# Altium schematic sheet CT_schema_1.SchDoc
size 714 x 518 mm
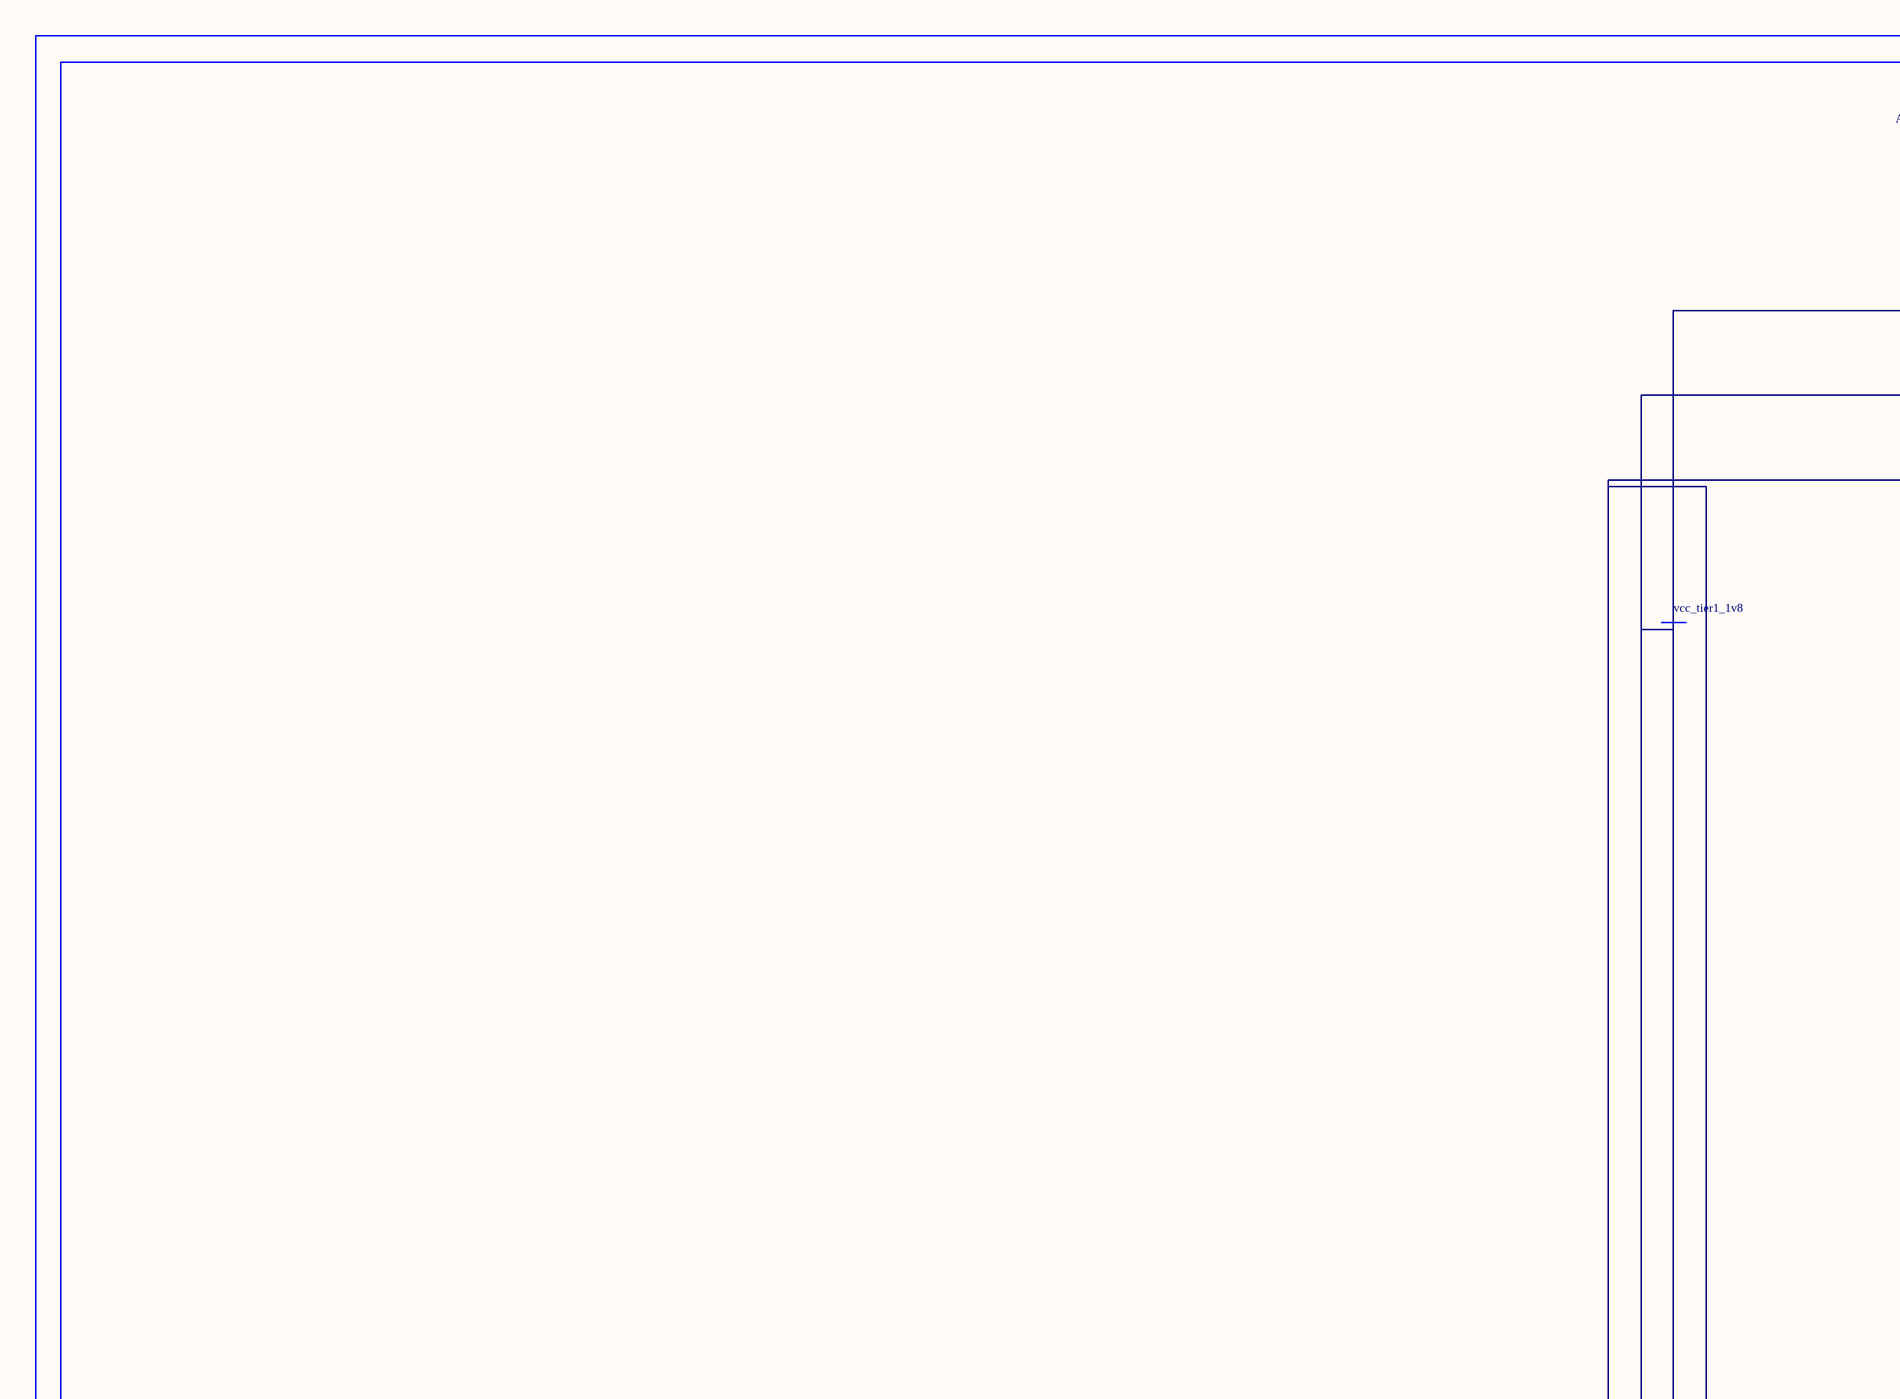
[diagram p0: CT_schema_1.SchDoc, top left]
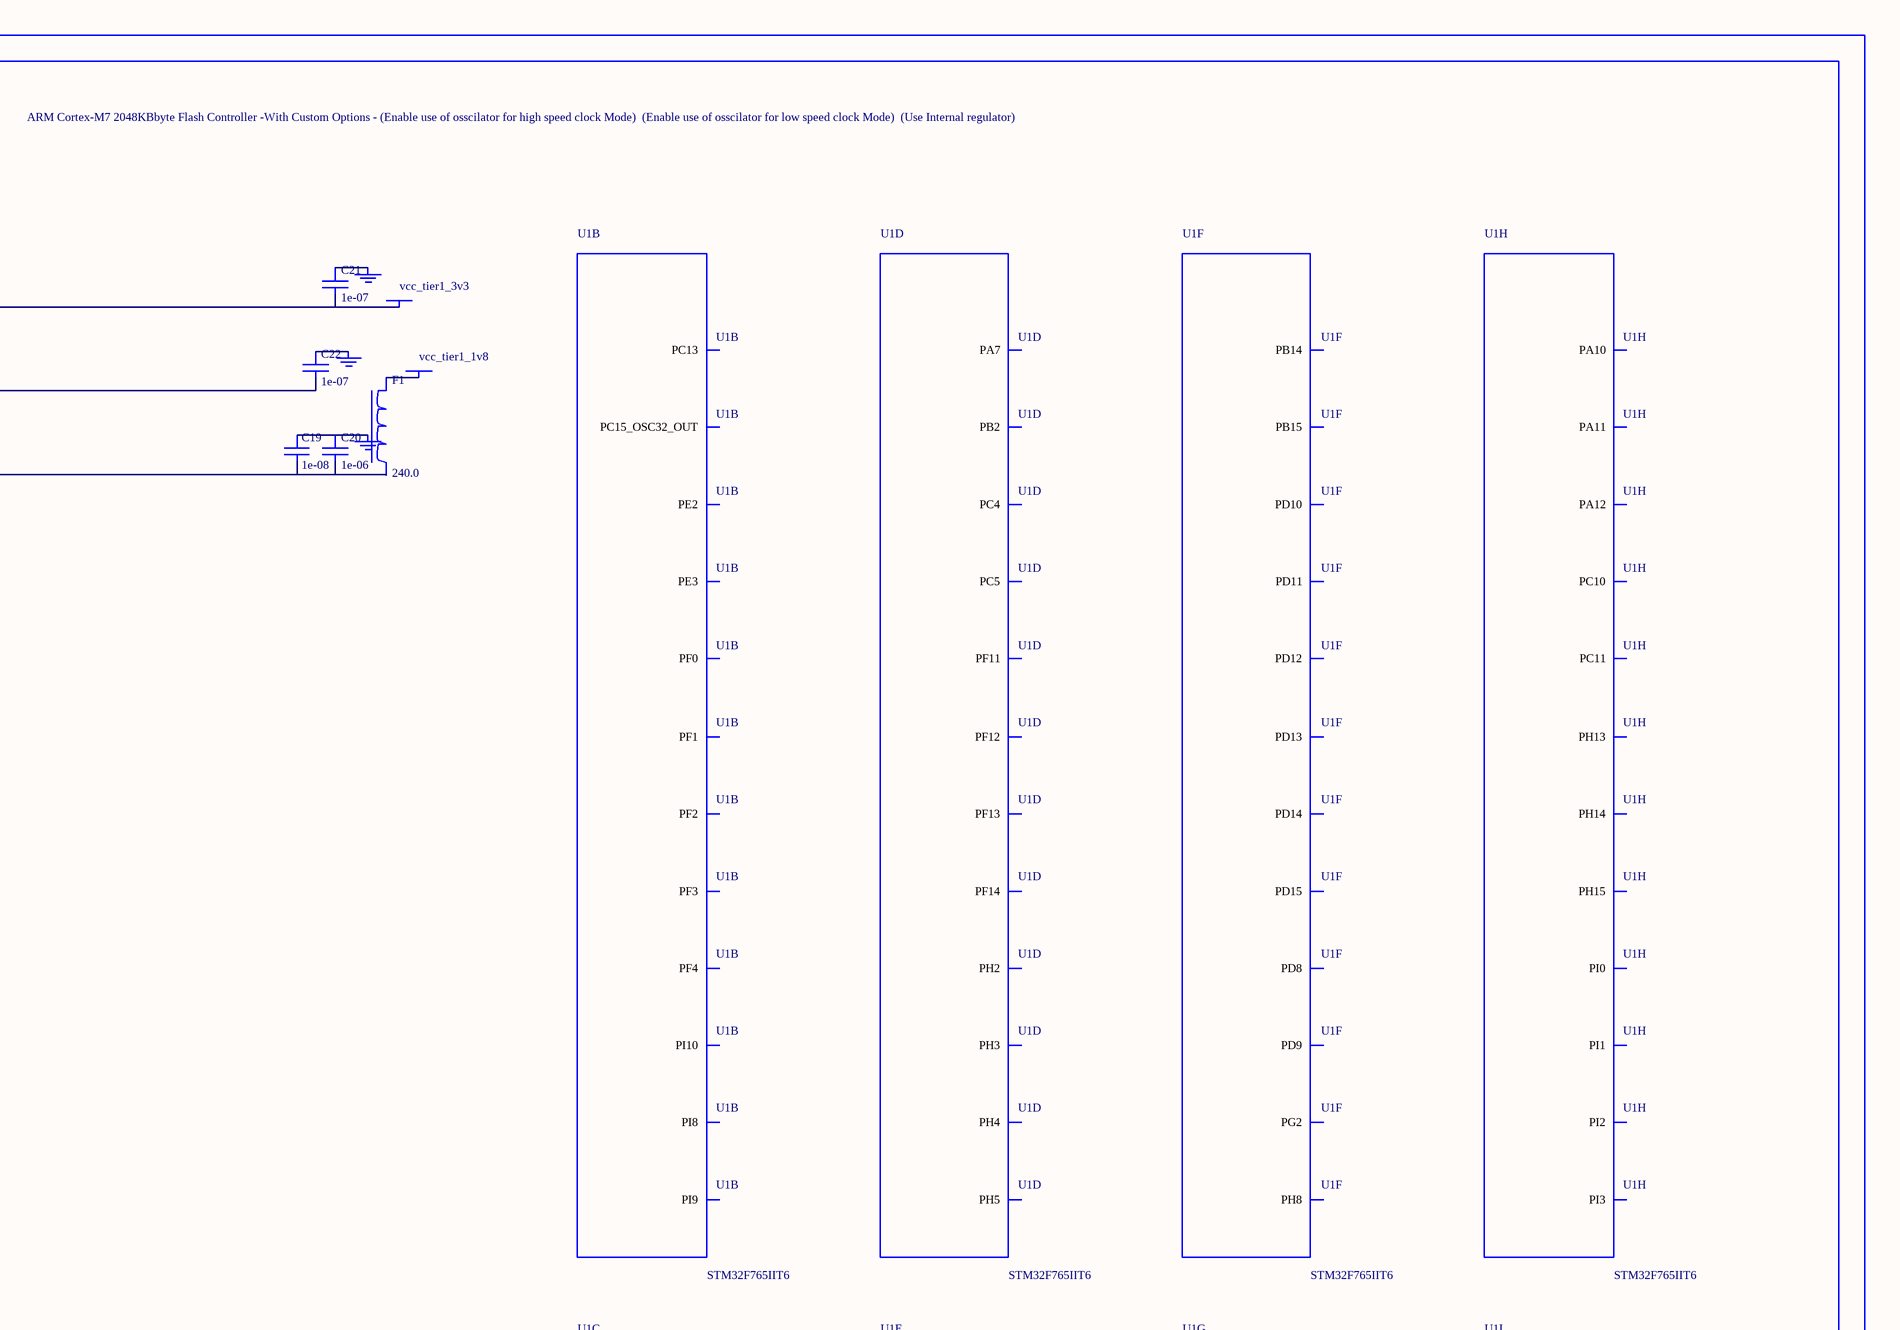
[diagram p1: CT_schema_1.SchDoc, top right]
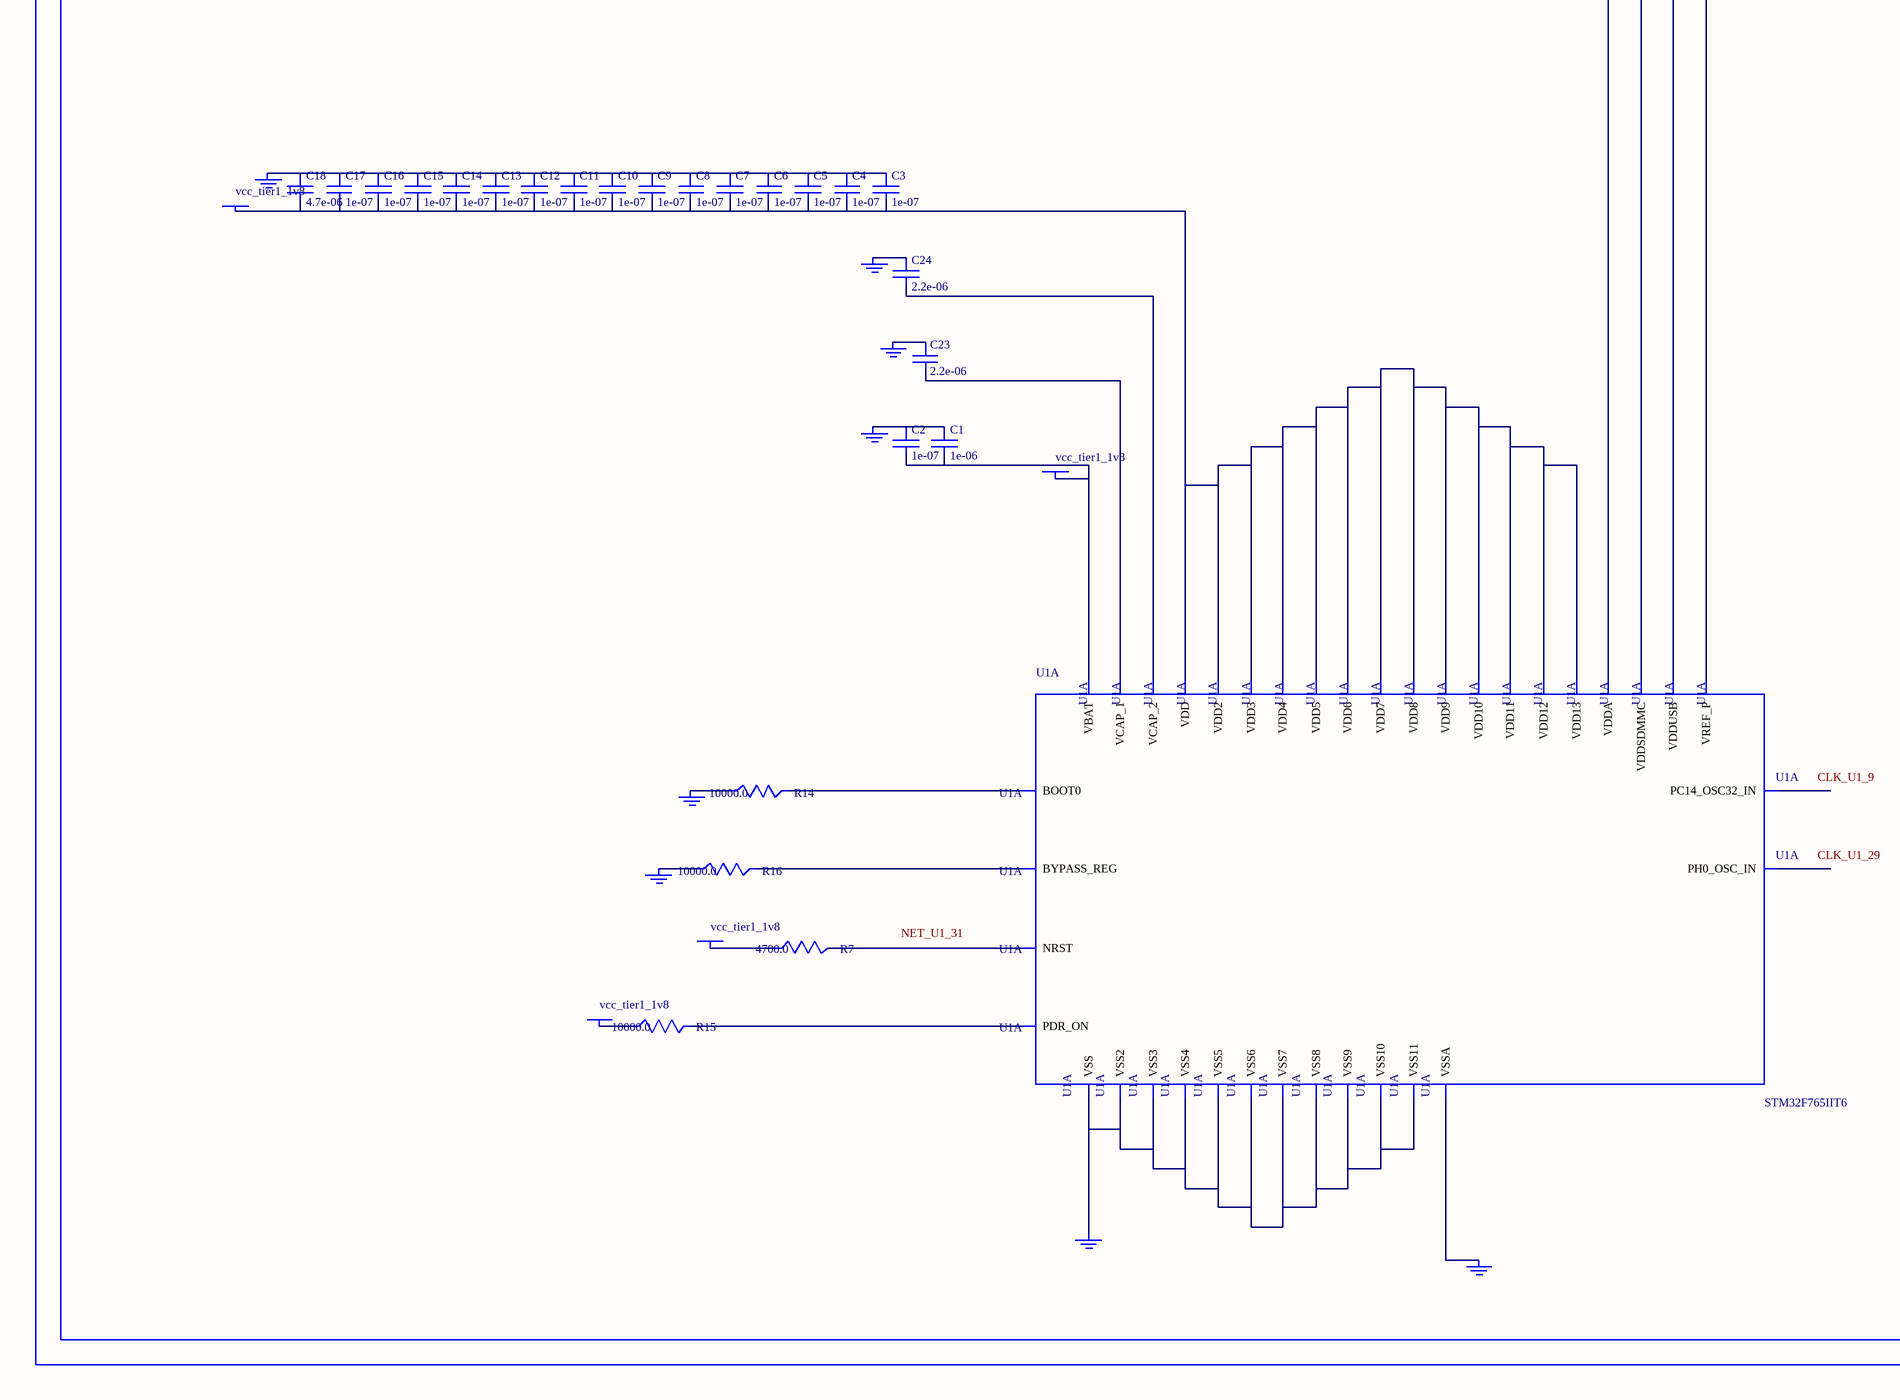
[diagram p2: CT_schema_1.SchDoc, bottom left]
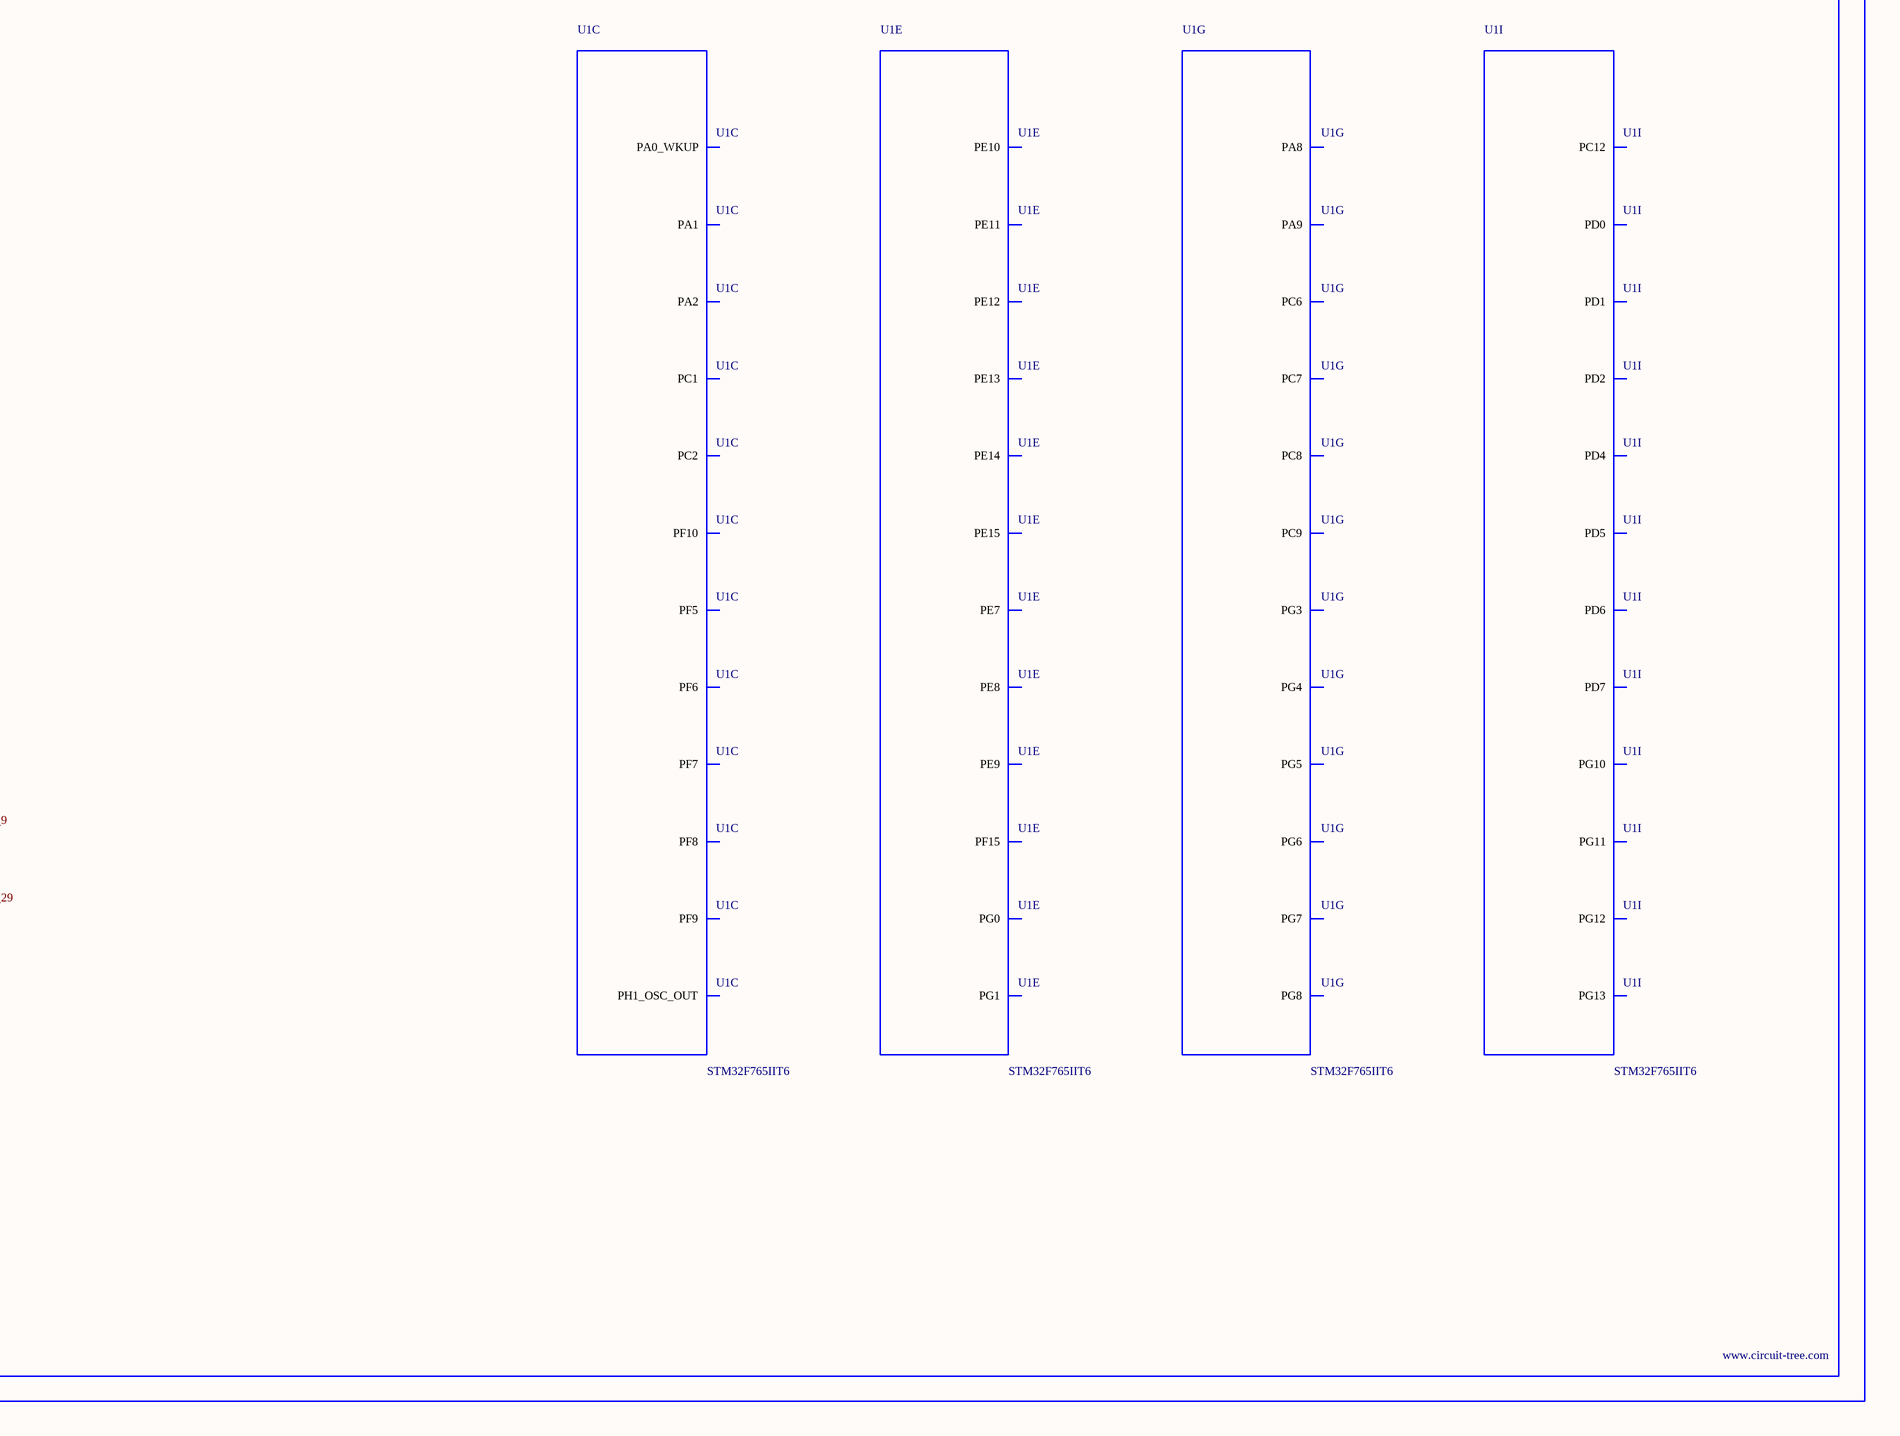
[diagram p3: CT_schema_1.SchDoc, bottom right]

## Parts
BORDER0  (no value)
C1  1e-06  [C0603]
C2  1e-07  [C0603]
C3  1e-07  [C0603]
C4  1e-07  [C0603]
C5  1e-07  [C0603]
C6  1e-07  [C0603]
C7  1e-07  [C0603]
C8  1e-07  [C0603]
C9  1e-07  [C0603]
C10  1e-07  [C0603]
C11  1e-07  [C0603]
C12  1e-07  [C0603]
C13  1e-07  [C0603]
C14  1e-07  [C0603]
C15  1e-07  [C0603]
C16  1e-07  [C0603]
C17  1e-07  [C0603]
C18  4.7e-06  [C0603]
C19  1e-08  [C0603]
C20  1e-06  [C0603]
C21  1e-07  [C0603]
C22  1e-07  [C0603]
C23  2.2e-06  [C0603]
C24  2.2e-06  [C0603]
F1  240.0  [L0603]
GND_INSTANCE_0_0  (no value)
GND_INSTANCE_0_1  (no value)
GND_INSTANCE_0_2  (no value)
GND_INSTANCE_0_3  (no value)
GND_INSTANCE_0_4  (no value)
GND_INSTANCE_0_5  (no value)
GND_INSTANCE_0_6  (no value)
GND_INSTANCE_0_7  (no value)
GND_INSTANCE_0_8  (no value)
GND_INSTANCE_0_9  (no value)
GND_INSTANCE_0_10  (no value)
POWER_INSTANCE_0_0  vcc_tier1_1v8
POWER_INSTANCE_0_1  vcc_tier1_1v8
POWER_INSTANCE_0_2  vcc_tier1_1v8
POWER_INSTANCE_0_3  vcc_tier1_3v3
POWER_INSTANCE_0_4  vcc_tier1_1v8
POWER_INSTANCE_0_5  vcc_tier1_1v8
POWER_INSTANCE_0_6  vcc_tier1_1v8
R7  4700.0  [R0603]
R14  10000.0  [R0603]
R15  10000.0  [R0603]
R16  10000.0  [R0603]
U1  STM32F765IIT6  [LQFP176]  (parts A,B,C,D,E,F,G,H,I of 12)

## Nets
NetC1_1: C1.1 C2.1 GND_INSTANCE_0_0.0(GND)
NetC1_2: C1.2 C2.2 POWER_INSTANCE_0_0.0(PWR) U1.6(VBAT)
NetC3_1: C3.1 C4.1 C5.1 C6.1 C7.1 C8.1 C9.1 C10.1 C11.1 C12.1 C13.1 C14.1 C15.1 C16.1 C17.1 C18.1 GND_INSTANCE_0_1.0(GND)
NetC3_2: C3.2 C4.2 C5.2 C6.2 C7.2 C8.2 C9.2 C10.2 C11.2 C12.2 C13.2 C14.2 C15.2 C16.2 C17.2 C18.2 POWER_INSTANCE_0_1.0(PWR) U1.15(VDD) U1.23(VDD2) U1.36(VDD3) U1.49(VDD4) U1.62(VDD5) U1.72(VDD6) U1.82(VDD7) U1.91(VDD8) U1.103(VDD9) U1.127(VDD10) U1.136(VDD11) U1.159(VDD12) U1.172(VDD13)
NetC19_1: C19.1 C20.1 GND_INSTANCE_0_3.0(GND)
NetC19_2: C19.2 C20.2 U1.38(VREF_P) U1.39(VDDA)
NetC21_1: C21.1 GND_INSTANCE_0_6.0(GND)
NetC21_2: C21.2 C22.2 POWER_INSTANCE_0_3.0(PWR) POWER_INSTANCE_0_4.0(PWR) U1.114(VDDUSB) U1.149(VDDSDMMC)
NetC22_1: C22.1 GND_INSTANCE_0_8.0(GND)
NetC23_1: C23.1 GND_INSTANCE_0_5.0(GND)
NetC23_2: C23.2 U1.81(VCAP_1)
NetC24_1: C24.1 GND_INSTANCE_0_7.0(GND)
NetC24_2: C24.2 U1.125(VCAP_2)
NetF1_1: F1.1 POWER_INSTANCE_0_2.0(PWR)
NetGND_INSTANCE_0_2_0: GND_INSTANCE_0_2.0(GND) U1.37(VSSA)
NetGND_INSTANCE_0_4_0: GND_INSTANCE_0_4.0(GND) R16.1
NetGND_INSTANCE_0_9_0: GND_INSTANCE_0_9.0(GND) R14.1
NetGND_INSTANCE_0_10_0: GND_INSTANCE_0_10.0(GND) U1.14(VSS) U1.22(VSS2) U1.61(VSS3) U1.71(VSS4) U1.90(VSS5) U1.102(VSS6) U1.113(VSS7) U1.126(VSS8) U1.135(VSS9) U1.148(VSS10) U1.158(VSS11)
NetPOWER_INSTANCE_0_5_0: POWER_INSTANCE_0_5.0(PWR) R15.1
NetPOWER_INSTANCE_0_6_0: POWER_INSTANCE_0_6.0(PWR) R7.1
NetR7_2: R7.2 U1.31(NRST)
NetR14_2: R14.2 U1.166(BOOT0)
NetR15_2: R15.2 U1.171(PDR_ON)
NetR16_2: R16.2 U1.48(BYPASS_REG)

Not connected (* = marked no-connect by the designer): F1 2; U1 1(PE2) 2(PE3) 7(PI8) 8(PC13) 9(PC14_OSC32_IN) 10(PC15_OSC32_OUT) 11(PI9) 12(PI10) 16(PF0) 17(PF1) 18(PF2) 19(PF3) 20(PF4) 21(PF5) 24(PF6) 25(PF7) 26(PF8) 27(PF9) 28(PF10) 29(PH0_OSC_IN) 30(PH1_OSC_OUT) 33(PC1) 34(PC2) 40(PA0_WKUP) 41(PA1) 42(PA2) 43(PH2) 44(PH3) 45(PH4) 46(PH5) 53(PA7) 54(PC4) 55(PC5) 58(PB2) 59(PF11) 60(PF12) 63(PF13) 64(PF14) 65(PF15) 66(PG0) 67(PG1) 68(PE7) 69(PE8) 70(PE9) 73(PE10) 74(PE11) 75(PE12) 76(PE13) 77(PE14) 78(PE15) 85(PH8) 94(PB14) 95(PB15) 96(PD8) 97(PD9) 98(PD10) 99(PD11) 100(PD12) 101(PD13) 104(PD14) 105(PD15) 106(PG2) 107(PG3) 108(PG4) 109(PG5) 110(PG6) 111(PG7) 112(PG8) 115(PC6) 116(PC7) 117(PC8) 118(PC9) 119(PA8) 120(PA9) 121(PA10) 122(PA11) 123(PA12) 128(PH13) 129(PH14) 130(PH15) 131(PI0) 132(PI1) 133(PI2) 134(PI3) 139(PC10) 140(PC11) 141(PC12) 142(PD0) 143(PD1) 144(PD2) 146(PD4) 147(PD5) 150(PD6) 151(PD7) 153(PG10) 154(PG11) 155(PG12) 156(PG13)

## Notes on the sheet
- Labels drawn without touching a wire or pin: CLK_U1_9, CLK_U1_29, NET_U1_31

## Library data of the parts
BORDER0 = BORDER_PAGE0
C1 C20 = C0603C105K3RACTU
C2-C17 C21 C22 = 06035C104K4Z2A
C18 = GRM188R6YA475KE15D
C19 = 06035C103K4Z2A
C23 C24 = C0603C225K8RACTU
F1 = Z0603C241ASMST
GND_INSTANCE_0_0-GND_INSTANCE_0_10 = GND
POWER_INSTANCE_0_0-POWER_INSTANCE_0_6 = PWR
R7 = RC0603JR-074K7L
R14-R16 = RC0603JR-0710KL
